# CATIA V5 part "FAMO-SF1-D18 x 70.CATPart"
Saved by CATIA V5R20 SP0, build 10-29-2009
Part number: FAMO-SF1-D18 x 70
Definition: NONE
Nomenclature: FAMO-SF1-D18 x 70
Source: Unknown
Description: FAMO-SF1-D18 x 70
Bounding box of the stored display mesh (mm): x -43 to 27, y -17 to 17, z -17 to 17
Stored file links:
  C:\Users\Utente\Desktop\IO LAVORO\3D X SITO CF\X SITO\FAMO\FAMO-SF1-D18 x 70.CATPart
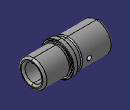
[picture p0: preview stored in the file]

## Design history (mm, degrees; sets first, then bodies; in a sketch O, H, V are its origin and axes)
Body1 "FAMO-SF1-D18 x 70" (main body)
  Solid1: solid without history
